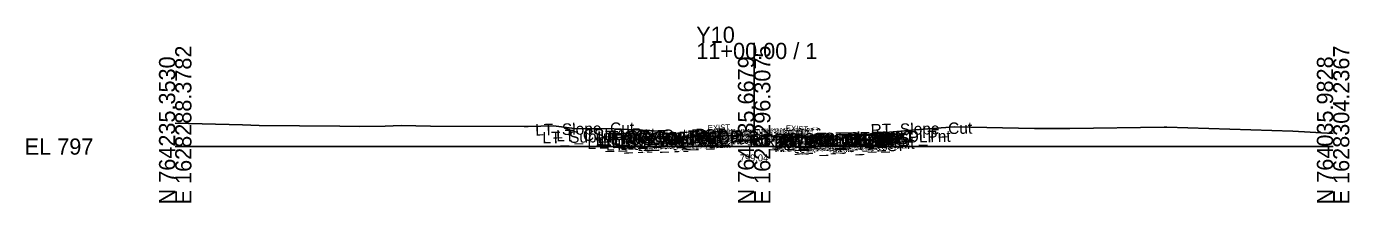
# Model space of a CAD drawing. Extents: x -26 to 203, y -10 to 4017.
# Drawn here: x -25.7 to 202.8, y 1990.3 to 2020.8 of the extents above; entities that cross this region are included whole.
import ezdxf

# ---------------------------------------------------------------- set-up
doc = ezdxf.new("R2010")
doc.units = 0
for name, color, linetype in [('Default', 7, 'Continuous'), ('Exist Cross Section Cell', 7, 'Continuous'), ('Exist XS Center Line Elevation Label', 7, 'Continuous'), ('Exist XS Ground Line', 7, 'Continuous'), ('Prop XS SE Text', 7, 'Continuous'), ('Scratch_Level_0', 7, 'Continuous')]:
    doc.layers.add(name, color=color, linetype=linetype)

msp = doc.modelspace()

# ---------------------------------------------------------------- linework, layer by layer
at = {"layer": 'Exist Cross Section Cell'}
for p, q in [((100, 2000), (100, 2017.95)), ((0, 2000), (100, 2000)), ((100, 2000), (200, 2000))]:
    msp.add_line(p, q, dxfattribs=at)
at = {"layer": 'Exist XS Ground Line'}
msp.add_lwpolyline([(0, 2004.06), (11.63, 2003.76), (14.48, 2003.67), (28.46, 2003.54), (31.8, 2003.45), (36.24, 2003.52), (39.03, 2003.63), (44.1, 2003.56), (60.3, 2003.45), (60.94, 2003.47), (65.35, 2003.59), (68.99, 2003.14), (75.74, 2003.07), (82, 2002.79), (83.29, 2002.64), (86.23, 2001.97), (87.26, 2001.7), (87.63, 2001.58), (98.05, 2001.98), (100.01, 2002.04), (103.98, 2001.8), (114.27, 2001.16), (115.23, 2001.47), (115.71, 2001.67), (118.15, 2002.02), (123.36, 2002.47), (129.18, 2002.99), (134.65, 2003.4), (148.44, 2003.12), (151.27, 2003.1), (154.5, 2003.12), (170.84, 2003.36), (171.3, 2003.34), (193.05, 2002.64), (200, 2002.26)], dxfattribs=at)

# ---------------------------------------------------------------- texts
at = {"layer": 'Default'}
msp.add_text('-', height=0.0001, dxfattribs=at).set_placement((0, 2000))
at = {"layer": 'Exist Cross Section Cell'}
for s, p in [('Y10', (90, 2017.95)), ('11+00.00 / 1', (90, 2015.15)), ('EL 797', (-26, 1998.6))]:
    msp.add_text(s, height=2.8, dxfattribs=at).set_placement(p)
for s, p in [('E 1628288.3782', (2.8, 1990)), ('E 1628296.3075', (102.8, 1990)), ('E 1628304.2367', (202.8, 1990)), ('N 764235.3530', (0, 1990)), ('N 764135.6679', (100, 1990)), ('N 764035.9828', (200, 1990))]:
    msp.add_text(s, height=2.8, rotation=90, dxfattribs=at).set_placement(p)
at = {"layer": 'Exist XS Center Line Elevation Label'}
msp.add_text('799.04', height=1.2, dxfattribs=at).set_placement((97.52, 1997.44))
at = {"layer": 'Prop XS SE Text'}
for rotation, p in [(2.2906, (92.01, 2002.72)), (356.5664, (105.43, 2002.72))]:
    msp.add_text('EXIST.', height=1, rotation=rotation, dxfattribs=at).set_placement(p)
at = {"layer": 'Scratch_Level_0'}
for s, p in [('LT_Slope_Cut', (62.2, 2001.9)), ('LT_Sub_Trench_Out_DLT', (63.44, 2000.54)), ('LT_CSLP_Pnt', (65.83, 2000.88)), ('LT_CG1_Shelf_Out', (71.21, 1999.57)), ('LT_PV_Sub_Tie_Out', (72.62, 2000.28)), ('LT_CG_Top_Face', (72.92, 2000.63)), ('LT_CG_Top_BOC', (73.44, 2000.65)), ('LT_CG_Bot_BOC', (73.47, 1999.63)), ('LT_CG_Top_Gut', (73.89, 2000.15)), ('LT_PV_OEEOP_EG', (75.2, 2000.33)), ('LT_PV2_OEEOP', (76.96, 2000.08)), ('LT_PV3_OEEOP', (76.96, 1999.75)), ('LT_PV1_OEEOP', (77.53, 2000.22)), ('LT_CG_Bot_IE', (77.57, 1999.76)), ('LT_PV2_OEOT', (77.83, 2000.1)), ('LT_PV3_OEOT', (77.83, 1999.77)), ('LT_PV1_OEOT', (78.4, 2000.36)), ('RT_PV_IEEOP_EG', (88.16, 2000.8)), ('LT_PV_IEEOP_EG', (88.21, 2000.8)), ('RT_PV2_IEEOP', (89.93, 2000.59)), ('RT_PV3_IEEOP', (89.93, 2000.26)), ('LT_PV2_IEEOP', (89.97, 2000.59)), ('LT_PV3_IEEOP', (89.97, 2000.26)), ('RT_PV1_IEEOP', (90.49, 2000.72)), ('LT_PV1_IEEOP', (90.54, 2000.73)), ('PV2_PGL', (93.93, 2000.67)), ('PV1_PGL', (94.49, 2000.93)), ('RT_PV_Sub_Tie_Out', (99.17, 1999.86)), ('RT_Sub_Trench_Out_DLT', (99.63, 2000.14)), ('RT_PV_OEEOP_EG', (101.79, 1999.91)), ('RT_CG_Top_Face', (103.5, 2000.23)), ('RT_PV2_OEEOP', (103.55, 1999.72)), ('RT_PV1_OEEOP', (104.12, 1999.86)), ('RT_PV2_OEOT', (104.41, 1999.74)), ('RT_CG_Top_Gut', (104.48, 1999.75)), ('RT_PV1_OEOT', (104.98, 2000)), ('RT_CG_Top_BOC', (105.03, 2000.25)), ('RT_CSLP_Pnt', (116.42, 2000.48)), ('RT_Slope_Cut', (120.14, 2001.89)), ('LT_Sub_OEOP', (74.42, 1999.3)), ('LT_Sub_OEEOP', (76.87, 1999.41)), ('LT_Sub_OEOT', (77.74, 1999.43)), ('RT_Sub_OEEOP', (103.45, 1999.05)), ('RT_PV3_OEEOP', (103.55, 1999.39)), ('RT_CG1_Shelf_Out', (103.79, 1999.15)), ('RT_CG_Bot_IE', (104.15, 1999.4)), ('RT_Sub_OEOT', (104.32, 1999.07)), ('RT_PV3_OEOT', (104.41, 1999.4)), ('RT_CG_Bot_BOC', (105.06, 1999.22)), ('RT_Sub_OEOP', (107.71, 1998.87))]:
    msp.add_text(s, height=2, rotation=1.1458, dxfattribs=at).set_placement(p)

doc.saveas('drawing.dxf')
